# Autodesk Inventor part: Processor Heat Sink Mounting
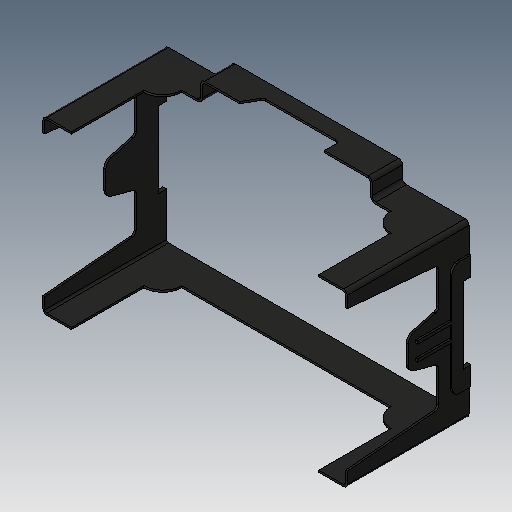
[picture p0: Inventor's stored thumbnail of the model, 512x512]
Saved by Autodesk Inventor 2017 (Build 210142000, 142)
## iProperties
Created: 2005-11
Part Number: Processor Heat Sink Mounting
Material: Generic
Document SubType Name: Modeling
Designer: DanielSeverino
Density: 1 g/cm^3
Appearance: Default
Author: DanielSeverino
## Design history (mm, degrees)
feature "Solid1"
body "Solid2"
